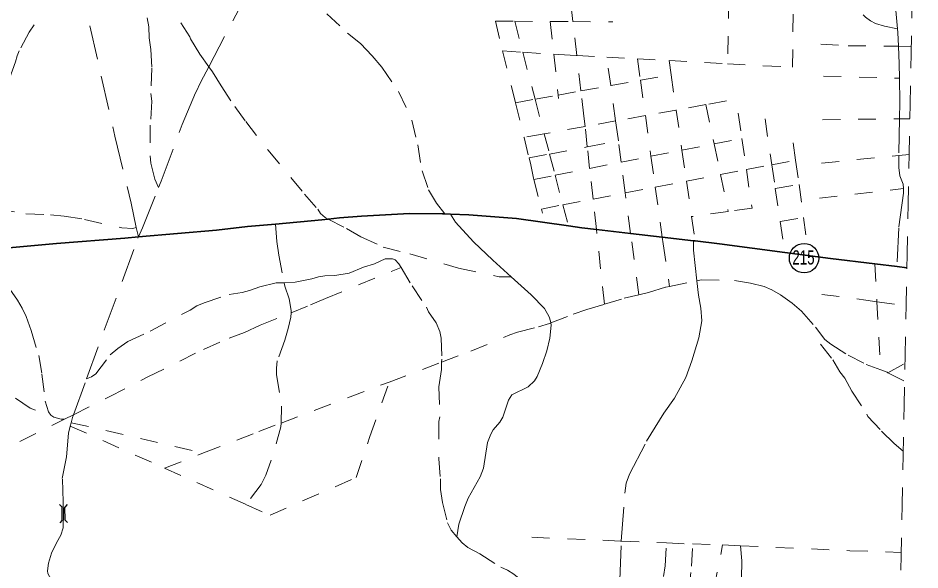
# Model space of a CAD drawing. Extents: x 783.4 to 809.8, y 7536.4 to 7564.6.
# Drawn here: x 804.65 to 809.73, y 7556.11 to 7559.21 of the extents above; entities that cross this region are included whole.
import ezdxf
from ezdxf.enums import TextEntityAlignment as Align

# ---------------------------------------------------------------- set-up
doc = ezdxf.new("R2010")
doc.units = 0
doc.header["$LTSCALE"] = 0.032
for name, pattern in [('DOTTED', [1.5, 0.3, -1.2]), ('LONG_DASHED', [7.5, 6, -1.5]), ('MEDIUM_DASHED', [4.5, 3, -1.5]), ('SHORT_DASHED', [2.7, 1.5, -1.2])]:
    doc.linetypes.add(name, pattern=pattern)
for name, color, linetype, lineweight in [('10', 7, 'Continuous', 25), ('13', 7, 'Continuous', 25), ('2', 7, 'Continuous', 35), ('35', 7, 'SHORT_DASHED', 13), ('5', 7, 'LONG_DASHED', 13), ('6', 7, 'MEDIUM_DASHED', 13), ('7', 7, 'DOTTED', 13)]:
    doc.layers.add(name, color=color, linetype=linetype, lineweight=lineweight)
doc.layers.add('61', color=7, linetype='Continuous')

msp = doc.modelspace()

# ---------------------------------------------------------------- linework, layer by layer
at = {"layer": '10'}
for p, q in [((804.926, 7556.4746), (804.9122, 7556.4602)), ((804.9135, 7556.3862), (804.9122, 7556.4602)), ((804.8975, 7556.386), (804.8835, 7556.3717)), ((804.9278, 7556.3725), (804.9135, 7556.3862))]:
    msp.add_line(p, q, dxfattribs=at)
msp.add_lwpolyline([(804.8975, 7556.386), (804.8962, 7556.46), (804.8818, 7556.4739)], dxfattribs=at)
at = {"layer": '13'}
msp.add_circle((809.0752, 7557.8616), 0.083, dxfattribs=at)
at = {"layer": '2'}
for p, q in [((807.9054, 7558.0226), (808.0984, 7558.0003)), ((809.4733, 7557.8296), (809.5985, 7557.8142)), ((809.5985, 7557.8142), (809.6541, 7557.8074))]:
    msp.add_line(p, q, dxfattribs=at)
for points in [[(806.0988, 7558.0538), (806.3597, 7558.0774), (806.3951, 7558.0818)], [(806.3951, 7558.0818), (806.4589, 7558.0896), (806.5822, 7558.099), (806.8523, 7558.1127), (807.0397, 7558.1108), (807.0517, 7558.1104), (807.0833, 7558.1093)], [(807.0833, 7558.1093), (807.1865, 7558.1056), (807.4551, 7558.0849), (807.7478, 7558.0429)], [(805.3268, 7557.9814), (805.7654, 7558.0201), (805.9403, 7558.0394), (806.0988, 7558.0538)], [(807.7478, 7558.0429), (807.8244, 7558.0319), (807.9054, 7558.0226)], [(804.3449, 7557.8967), (804.8644, 7557.9441), (805.2498, 7557.9746), (805.3268, 7557.9814)], [(808.0984, 7558.0003), (808.2761, 7557.9798), (808.4519, 7557.9596), (808.4616, 7557.9585)], [(808.4616, 7557.9585), (808.5991, 7557.9426), (808.9668, 7557.8942)], [(808.9668, 7557.8942), (809.224, 7557.8603), (809.4733, 7557.8296)]]:
    msp.add_lwpolyline(points, dxfattribs=at)
at = {"layer": '35'}
msp.add_lwpolyline([(809.6166, 7555.9048), (809.6222, 7556.1875), (809.6278, 7556.4702), (809.6333, 7556.7528), (809.6389, 7557.0354), (809.6445, 7557.3181), (809.65, 7557.6007), (809.6556, 7557.8834), (809.6612, 7558.166), (809.6667, 7558.4487), (809.6722, 7558.7314), (809.6778, 7559.014), (809.6834, 7559.2967), (809.6889, 7559.5793), (809.6945, 7559.862), (809.7001, 7560.1446), (809.7056, 7560.4272), (809.7112, 7560.7099), (809.7168, 7560.9926), (809.7223, 7561.2752), (809.7278, 7561.5578)], dxfattribs=at)
at = {"layer": '5'}
for p, q in [((809.6123, 7558.6462), (809.6094, 7558.4397)), ((804.96, 7556.9796), (805.0341, 7557.1823)), ((804.9429, 7556.9162), (804.9474, 7556.935))]:
    msp.add_line(p, q, dxfattribs=at)
for points in [[(804.8235, 7560.1454), (804.8615, 7559.9788), (804.9873, 7559.4549), (805.1943, 7558.5495), (805.2861, 7558.1712), (805.3146, 7558.0338), (805.3268, 7557.9814)], [(805.7227, 7558.9393), (806.0525, 7559.5689), (806.0625, 7559.5988), (806.0706, 7559.6187)], [(809.5671, 7559.3876), (809.5803, 7559.3526), (809.5858, 7559.3199), (809.6006, 7559.1539)], [(809.6006, 7559.1539), (809.6025, 7559.1324), (809.6065, 7559.0546)], [(809.6065, 7559.0546), (809.6116, 7558.9558), (809.6124, 7558.8745)], [(805.4405, 7558.2593), (805.4546, 7558.2949), (805.5734, 7558.6149), (805.6491, 7558.7939), (805.6781, 7558.8543), (805.7227, 7558.9393)], [(809.6124, 7558.8745), (809.6136, 7558.7405), (809.6123, 7558.6462)], [(809.6094, 7558.4397), (809.6084, 7558.3718), (809.6144, 7558.3261), (809.6334, 7558.2785), (809.6346, 7558.2535)], [(805.3268, 7557.9814), (805.3504, 7558.0318), (805.4405, 7558.2593)], [(809.6346, 7558.2535), (809.6358, 7558.2279), (809.6084, 7558.0319), (809.5985, 7557.8142)], [(807.4261, 7557.7566), (807.3215, 7557.85), (807.2135, 7557.9532), (807.1123, 7558.0645), (807.0833, 7558.1093)], [(805.0341, 7557.1823), (805.3238, 7557.9749), (805.3268, 7557.9814)], [(808.4716, 7557.7342), (808.453, 7557.906), (808.4519, 7557.9596)], [(807.6494, 7557.4967), (807.6479, 7557.5076), (807.6399, 7557.5316), (807.6135, 7557.5788), (807.5391, 7557.6556), (807.4261, 7557.7566)], [(808.0458, 7556.2684), (808.0654, 7556.5377), (808.0741, 7556.5941), (808.0916, 7556.6443), (808.1882, 7556.831), (808.2854, 7556.9888), (808.3448, 7557.074), (808.4088, 7557.1897), (808.4426, 7557.2825), (808.4816, 7557.413), (808.4991, 7557.5091), (808.4933, 7557.5801), (808.4804, 7557.6532), (808.4716, 7557.7342)], [(807.1205, 7556.2923), (807.1316, 7556.3641), (807.1639, 7556.4628), (807.1839, 7556.5108), (807.2503, 7556.6308), (807.2695, 7556.6788), (807.2927, 7556.8228), (807.3103, 7556.8708), (807.3247, 7556.8948), (807.3623, 7556.938), (807.3783, 7556.9668), (807.4111, 7557.0628), (807.4303, 7557.0916), (807.5223, 7557.1372), (807.5567, 7557.1708), (807.5719, 7557.1956), (807.6023, 7557.2676), (807.6263, 7557.3396), (807.6431, 7557.4116), (807.6511, 7557.4836), (807.6494, 7557.4967)], [(804.9474, 7556.935), (804.9545, 7556.9646), (804.96, 7556.9796)], [(805.1669, 7555.6141), (805.0254, 7555.7291), (804.9886, 7555.7843), (804.93, 7555.8966), (804.8348, 7556.0526), (804.8171, 7556.0853), (804.8145, 7556.1014), (804.8192, 7556.1442), (804.8373, 7556.1997), (804.8653, 7556.2589), (804.8894, 7556.3012), (804.9024, 7556.3425), (804.9054, 7556.4252), (804.8979, 7556.6211), (804.9209, 7556.7424), (804.9334, 7556.8763), (804.9429, 7556.9162)], [(808.0438, 7555.8586), (808.0374, 7556.0498), (808.0456, 7556.2659), (808.0458, 7556.2684)]]:
    msp.add_lwpolyline(points, dxfattribs=at)
at = {"layer": '6'}
for p, q in [((808.3169, 7557.7027), (808.4716, 7557.7342)), ((806.7385, 7557.1638), (807.0341, 7557.276)), ((809.5475, 7557.2167), (809.6415, 7557.168)), ((806.1296, 7556.9327), (806.7385, 7557.1638)), ((804.9429, 7556.9162), (805.4737, 7556.6792)), ((804.9474, 7556.935), (805.6938, 7556.7646)), ((805.4737, 7556.6792), (805.6938, 7556.7646)), ((805.4737, 7556.6792), (805.9316, 7556.4748))]:
    msp.add_line(p, q, dxfattribs=at)
for points in [[(808.4716, 7557.7342), (808.4971, 7557.7394), (808.6832, 7557.7362), (808.7737, 7557.7215), (808.8502, 7557.7019), (808.8937, 7557.6824), (808.9422, 7557.655), (809.0073, 7557.6085), (809.0613, 7557.5627), (809.139, 7557.4739), (809.1912, 7557.4042), (809.2252, 7557.3765), (809.3229, 7557.3147), (809.4257, 7557.2634), (809.5075, 7557.2324)], [(808.1439, 7557.6554), (808.1988, 7557.6685), (808.2971, 7557.6987), (808.3169, 7557.7027)], [(807.9513, 7557.6025), (808.0614, 7557.6358), (808.1439, 7557.6554)], [(807.6494, 7557.4967), (807.7744, 7557.5461), (807.8509, 7557.5722), (807.9513, 7557.6025)], [(807.0341, 7557.276), (807.1978, 7557.3381), (807.4187, 7557.4295), (807.4604, 7557.4441), (807.5795, 7557.4744), (807.6422, 7557.4939), (807.6494, 7557.4967)], [(809.5075, 7557.2324), (809.5437, 7557.2187), (809.5475, 7557.2167)], [(805.9316, 7556.4748), (806.0677, 7556.414), (806.5535, 7556.6272), (806.6304, 7556.8575), (806.7385, 7557.1638)], [(805.6938, 7556.7646), (806.0038, 7556.8849), (806.1296, 7556.9327)]]:
    msp.add_lwpolyline(points, dxfattribs=at)
at = {"layer": '7'}
for p, q in [((807.773, 7559.1938), (807.7549, 7559.348)), ((808.6507, 7559.3119), (808.6441, 7558.9564)), ((807.3365, 7559.1958), (807.4454, 7559.1953)), ((807.4454, 7559.1953), (807.6461, 7559.1944)), ((807.4454, 7559.1953), (807.491, 7559.0214)), ((807.6461, 7559.1944), (807.6658, 7559.0097)), ((807.7955, 7559.0024), (807.773, 7559.1938)), ((809.6065, 7559.0546), (809.6786, 7559.0538)), ((807.3777, 7559.029), (807.4498, 7558.7366)), ((807.3777, 7559.029), (807.491, 7559.0214)), ((807.491, 7559.0214), (807.6658, 7559.0097)), ((807.491, 7559.0214), (807.5605, 7558.7566)), ((807.6658, 7559.0097), (807.6902, 7558.7799)), ((807.8189, 7558.8031), (807.7955, 7559.0024)), ((807.9861, 7558.8332), (807.9638, 7558.9933)), ((808.1373, 7558.9839), (808.3146, 7558.9743)), ((808.1373, 7558.9839), (808.1539, 7558.8635)), ((808.3146, 7558.9743), (808.6441, 7558.9564)), ((808.1539, 7558.8635), (808.3262, 7558.8945)), ((807.9861, 7558.8332), (808.1539, 7558.8635)), ((808.1539, 7558.8635), (808.1814, 7558.6646)), ((809.1848, 7558.8867), (809.6124, 7558.8745)), ((807.6902, 7558.7799), (807.8189, 7558.8031)), ((807.8189, 7558.8031), (807.9861, 7558.8332)), ((807.4498, 7558.7366), (807.5605, 7558.7566)), ((807.5605, 7558.7566), (807.6902, 7558.7799)), ((807.6902, 7558.7799), (807.6923, 7558.7603)), ((807.4498, 7558.7366), (807.498, 7558.5414)), ((808.3549, 7558.6959), (808.1814, 7558.6646)), ((808.3549, 7558.6959), (808.3876, 7558.4697)), ((808.5222, 7558.7261), (808.5683, 7558.5054)), ((808.1814, 7558.6646), (808.2131, 7558.4352)), ((808.8552, 7558.6462), (808.8936, 7558.3878)), ((809.1798, 7558.6413), (809.6123, 7558.6462)), ((809.6123, 7558.6462), (809.6706, 7558.6469)), ((807.8419, 7558.6034), (807.6116, 7558.5619)), ((808.0139, 7558.6344), (807.8419, 7558.6034)), ((807.8545, 7558.4886), (807.8419, 7558.6034)), ((807.6116, 7558.5619), (807.6415, 7558.448)), ((808.5683, 7558.5054), (808.7249, 7558.5363)), ((807.6415, 7558.448), (807.8545, 7558.4886)), ((807.8545, 7558.4886), (808.0295, 7558.5219)), ((807.8677, 7558.3669), (807.8545, 7558.4886)), ((808.0453, 7558.402), (808.0295, 7558.5219)), ((808.3876, 7558.4697), (808.5683, 7558.5054)), ((808.5683, 7558.5054), (808.6044, 7558.3322)), ((809.0143, 7558.5105), (809.0277, 7558.4136)), ((807.6415, 7558.448), (807.6729, 7558.3284)), ((808.0453, 7558.402), (808.2131, 7558.4352)), ((808.2131, 7558.4352), (808.3876, 7558.4697)), ((808.2131, 7558.4352), (808.2371, 7558.2616)), ((808.3876, 7558.4697), (808.4128, 7558.2954)), ((809.1738, 7558.3969), (809.6094, 7558.4397)), ((809.6094, 7558.4397), (809.6666, 7558.4453)), ((807.8677, 7558.3669), (808.0453, 7558.402)), ((808.0682, 7558.2291), (808.0453, 7558.402)), ((808.7506, 7558.3603), (808.8936, 7558.3878)), ((808.8936, 7558.3878), (809.0277, 7558.4136)), ((807.6729, 7558.3284), (807.8677, 7558.3669)), ((807.8866, 7558.1942), (807.8677, 7558.3669)), ((808.4128, 7558.2954), (808.6044, 7558.3322)), ((808.6044, 7558.3322), (808.7506, 7558.3603)), ((808.6044, 7558.3322), (808.6478, 7558.1245)), ((807.5533, 7558.3048), (807.6729, 7558.3284)), ((807.6729, 7558.3284), (807.7167, 7558.1615)), ((808.2371, 7558.2616), (808.4128, 7558.2954)), ((808.4128, 7558.2954), (808.4418, 7558.0956)), ((807.8866, 7558.1942), (808.0682, 7558.2291)), ((808.0682, 7558.2291), (808.2371, 7558.2616)), ((808.0984, 7558.0003), (808.0682, 7558.2291)), ((808.2371, 7558.2616), (808.2761, 7557.9798)), ((808.9133, 7558.2548), (809.0467, 7558.276)), ((809.1629, 7558.2), (809.6346, 7558.2535)), ((807.7167, 7558.1615), (807.8866, 7558.1942)), ((807.9054, 7558.0226), (807.8866, 7558.1942)), ((807.5965, 7558.1384), (807.7167, 7558.1615)), ((807.5965, 7558.1384), (807.6023, 7558.1159)), ((807.7167, 7558.1615), (807.7478, 7558.0429)), ((808.4418, 7558.0956), (808.4616, 7557.9585)), ((808.941, 7558.0682), (809.0722, 7558.0915)), ((809.0722, 7558.0915), (809.0902, 7557.9612)), ((808.941, 7558.0682), (808.9668, 7557.8942)), ((807.9513, 7557.6025), (807.9054, 7558.0226)), ((808.1439, 7557.6554), (808.0984, 7558.0003)), ((809.4733, 7557.8296), (809.4855, 7557.6166)), ((809.4855, 7557.6166), (809.5075, 7557.2324)), ((809.4855, 7557.6166), (809.6499, 7557.5938)), ((809.5475, 7557.2167), (809.6435, 7557.2696)), ((807.5424, 7556.2896), (808.0458, 7556.2684))]:
    msp.add_line(p, q, dxfattribs=at)
for points in [[(805.2687, 7559.5748), (805.3412, 7559.4937), (805.4532, 7559.3525), (805.6168, 7559.108), (805.6198, 7559.0965), (805.6718, 7559.0109), (805.7227, 7558.9393)], [(805.2687, 7559.5748), (805.3762, 7559.2152), (805.3859, 7559.1637), (805.3873, 7559.1025), (805.3962, 7559.0364), (805.4018, 7558.9317), (805.3966, 7558.7891), (805.4022, 7558.7449), (805.3933, 7558.6113), (805.3923, 7558.4385), (805.396, 7558.396), (805.4183, 7558.3063), (805.4405, 7558.2593)], [(806.0844, 7559.5967), (806.1065, 7559.5736), (806.1963, 7559.4303), (806.1951, 7559.4245), (806.2535, 7559.3437), (806.3871, 7559.2373), (806.5047, 7559.1293), (806.5767, 7559.0701), (806.6423, 7559.0013), (806.6967, 7558.9373), (806.7911, 7558.7996), (806.8671, 7558.6396), (806.8991, 7558.4996), (806.9239, 7558.354), (806.9607, 7558.246), (807.0055, 7558.1708), (807.0517, 7558.1104)], [(807.2935, 7559.3698), (807.3365, 7559.1958), (807.3777, 7559.029)], [(808.6441, 7558.9564), (809.0101, 7558.9366), (809.0149, 7559.2974)], [(807.6461, 7559.1944), (807.773, 7559.1938), (807.9989, 7559.1927)], [(809.4086, 7559.2319), (809.4202, 7559.2182), (809.4491, 7559.1983), (809.478, 7559.1839), (809.529, 7559.1688), (809.6006, 7559.1539)], [(804.7401, 7559.1754), (804.7112, 7559.1345), (804.6558, 7559.0301), (804.643, 7559.0005), (804.6342, 7558.9669), (804.595, 7558.854), (804.5398, 7558.7332), (804.5126, 7558.6596), (804.4758, 7558.5844), (804.4462, 7558.4932), (804.4286, 7558.4212), (804.3918, 7558.3308), (804.3806, 7558.286), (804.3558, 7558.2212), (804.3326, 7558.1716), (804.3317, 7558.1682)], [(809.1694, 7559.0668), (809.3236, 7559.0578), (809.6065, 7559.0546)], [(807.6658, 7559.0097), (807.6913, 7559.008), (807.7955, 7559.0024)], [(807.7955, 7559.0024), (807.9638, 7558.9933), (808.1373, 7558.9839)], [(808.3146, 7558.9743), (808.3262, 7558.8945), (808.3549, 7558.6959)], [(805.7227, 7558.9393), (805.7435, 7558.91), (805.7917, 7558.8314), (805.8688, 7558.7166), (805.9308, 7558.6314), (806.0569, 7558.4693), (806.2613, 7558.2227), (806.3374, 7558.1368), (806.3522, 7558.1131), (806.3789, 7558.0902), (806.3951, 7558.0818)], [(807.8419, 7558.6034), (807.8355, 7558.6619), (807.8189, 7558.8031)], [(808.1814, 7558.6646), (808.0139, 7558.6344), (807.9861, 7558.8332)], [(807.5605, 7558.7566), (807.6116, 7558.5619), (807.498, 7558.5414)], [(808.6376, 7558.7469), (808.5222, 7558.7261), (808.3549, 7558.6959)], [(808.7042, 7558.6783), (808.7249, 7558.5363), (808.7506, 7558.3603)], [(808.0295, 7558.5219), (808.0276, 7558.5363), (808.0139, 7558.6344)], [(807.498, 7558.5414), (807.5265, 7558.4261), (807.6415, 7558.448)], [(807.5265, 7558.4261), (807.536, 7558.3875), (807.5516, 7558.3112), (807.5533, 7558.3048), (807.5965, 7558.1384)], [(808.8936, 7558.3878), (808.9133, 7558.2548), (808.941, 7558.0682)], [(809.0277, 7558.4136), (809.0467, 7558.276), (809.0722, 7558.0915)], [(808.7506, 7558.3603), (808.7822, 7558.1433), (808.6478, 7558.1245), (808.4418, 7558.0956)], [(804.3317, 7558.1682), (804.6933, 7558.1121), (804.8313, 7558.1059), (804.9092, 7558.0984), (805.0231, 7558.08), (805.2323, 7558.032), (805.2943, 7558.0282), (805.3146, 7558.0338)], [(806.3951, 7558.0818), (806.4976, 7558.0283), (806.5792, 7557.9809), (806.7043, 7557.9242), (806.8548, 7557.8852), (807.1297, 7557.8049), (807.3572, 7557.7572), (807.4261, 7557.7566)], [(806.0988, 7558.0538), (806.1069, 7557.9556), (806.1177, 7557.8779), (806.1479, 7557.7235)], [(808.2761, 7557.9798), (808.2813, 7557.9419), (808.3169, 7557.7027)], [(804.3449, 7557.8967), (804.3449, 7557.8967), (804.3745, 7557.8714), (804.4969, 7557.7942), (804.531, 7557.7685), (804.5896, 7557.7059), (804.6464, 7557.6242), (804.6724, 7557.5803), (804.6939, 7557.5337), (804.7228, 7557.4551), (804.7655, 7557.3128), (804.7833, 7557.2078), (804.8015, 7557.0565), (804.8201, 7556.9967), (804.8327, 7556.9779), (804.8505, 7556.9653), (804.8917, 7556.9553), (804.9104, 7556.9548)], [(804.7468, 7557.0054), (804.7168, 7557.0164), (804.431, 7557.2148), (804.2798, 7557.3156), (804.1302, 7557.446), (804.0294, 7557.5293), (803.6944, 7557.8226), (803.6756, 7557.8387)], [(806.1479, 7557.7235), (806.2083, 7557.7256), (806.3037, 7557.7444), (806.3407, 7557.7562), (806.3762, 7557.7624), (806.4324, 7557.7645), (806.5142, 7557.7766), (806.5933, 7557.8106), (806.6562, 7557.8293), (806.7157, 7557.857), (806.7579, 7557.8584), (806.7727, 7557.8515), (806.7927, 7557.83), (806.8057, 7557.8085)], [(806.1863, 7557.5545), (806.2961, 7557.5984), (806.38, 7557.6352), (806.8057, 7557.8085)], [(806.8057, 7557.8085), (806.8674, 7557.7065), (806.9488, 7557.5851), (806.961, 7557.5598), (807.0032, 7557.498), (807.0246, 7557.4488), (807.032, 7557.412), (807.0347, 7557.293), (807.0341, 7557.276)], [(805.0341, 7557.1823), (805.063, 7557.1925), (805.086, 7557.2094), (805.1669, 7557.3171), (805.2101, 7557.3525), (805.266, 7557.3917), (805.3925, 7557.4507), (805.6171, 7557.5696), (805.6563, 7557.5932), (805.6963, 7557.6106), (805.8383, 7557.6563), (805.9104, 7557.6684), (805.9526, 7557.6795), (806.0111, 7557.7004), (806.1021, 7557.7219), (806.1479, 7557.7235)], [(806.1479, 7557.7235), (806.1519, 7557.7031), (806.1762, 7557.6322), (806.1875, 7557.5676), (806.1863, 7557.5545)], [(809.1745, 7557.6579), (809.4233, 7557.6252), (809.4855, 7557.6166)], [(804.96, 7556.9796), (805.1615, 7557.0805), (805.3797, 7557.1929), (805.6938, 7557.348), (805.837, 7557.4108), (805.9235, 7557.4434), (806.0123, 7557.485), (806.1863, 7557.5545)], [(806.1863, 7557.5545), (806.1839, 7557.5288), (806.1703, 7557.4655), (806.1505, 7557.4005), (806.1086, 7557.2827), (806.1032, 7557.243), (806.105, 7557.2041), (806.133, 7557.0277), (806.1296, 7556.9327)], [(809.1685, 7557.3764), (809.2368, 7557.2892), (809.2768, 7557.222), (809.3048, 7557.1852), (809.3448, 7557.1132), (809.4288, 7556.9836), (809.4336, 7556.9692), (809.512, 7556.8876), (809.5832, 7556.8172), (809.6337, 7556.775)], [(807.0341, 7557.276), (807.0325, 7557.2341), (807.0177, 7557.1369), (807.0246, 7556.9687), (807.018, 7556.9417), (807.0184, 7556.7311), (807.027, 7556.6196), (807.0281, 7556.5589), (807.0392, 7556.486), (807.0673, 7556.3716), (807.0884, 7556.3296), (807.1205, 7556.2923)], [(804.1228, 7556.5605), (804.9104, 7556.9548), (804.96, 7556.9796)], [(806.1296, 7556.9327), (806.1289, 7556.9125), (806.0749, 7556.7233), (806.0447, 7556.6401), (806.0186, 7556.5861), (805.9316, 7556.4748)], [(807.1205, 7556.2923), (807.1498, 7556.2582), (807.1809, 7556.2318), (807.2497, 7556.1971), (807.368, 7556.1208), (807.4046, 7556.1045), (807.4401, 7556.083), (807.574, 7555.9755), (807.6066, 7555.9595), (807.717, 7555.921), (807.7876, 7555.8922), (807.8439, 7555.8586)], [(808.0458, 7556.2684), (808.3005, 7556.2577), (808.4473, 7556.252)], [(808.2472, 7555.8586), (808.2508, 7555.872), (808.2932, 7556.1285), (808.3005, 7556.2577)], [(808.3972, 7555.8576), (808.4064, 7555.8897), (808.4253, 7555.9914), (808.4418, 7556.1263), (808.4473, 7556.252)], [(808.4473, 7556.252), (808.6167, 7556.2466), (808.7168, 7556.2419)], [(808.5313, 7555.8553), (808.5668, 7555.9959), (808.6167, 7556.2466)], [(808.6862, 7555.8526), (808.7023, 7555.9216), (808.7224, 7556.0578), (808.7242, 7556.1565), (808.7168, 7556.2419)], [(808.7168, 7556.2419), (809.3338, 7556.2143), (809.6225, 7556.2045)]]:
    msp.add_lwpolyline(points, dxfattribs=at)

# ---------------------------------------------------------------- texts
at = {"layer": '61', "width": 0.7}
msp.add_text('215', height=0.08, dxfattribs=at).set_placement((809.0719, 7557.8258), align=Align.CENTER)

doc.saveas('drawing.dxf')
